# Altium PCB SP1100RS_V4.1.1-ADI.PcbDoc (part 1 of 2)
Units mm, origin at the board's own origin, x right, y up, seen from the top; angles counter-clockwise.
Board outline 126.12 x 87.13 mm, 4 copper layers (TopLayer, GND, PWR, BottomLayer); 154 components, 100 nets, 516 pads, 161 vias.
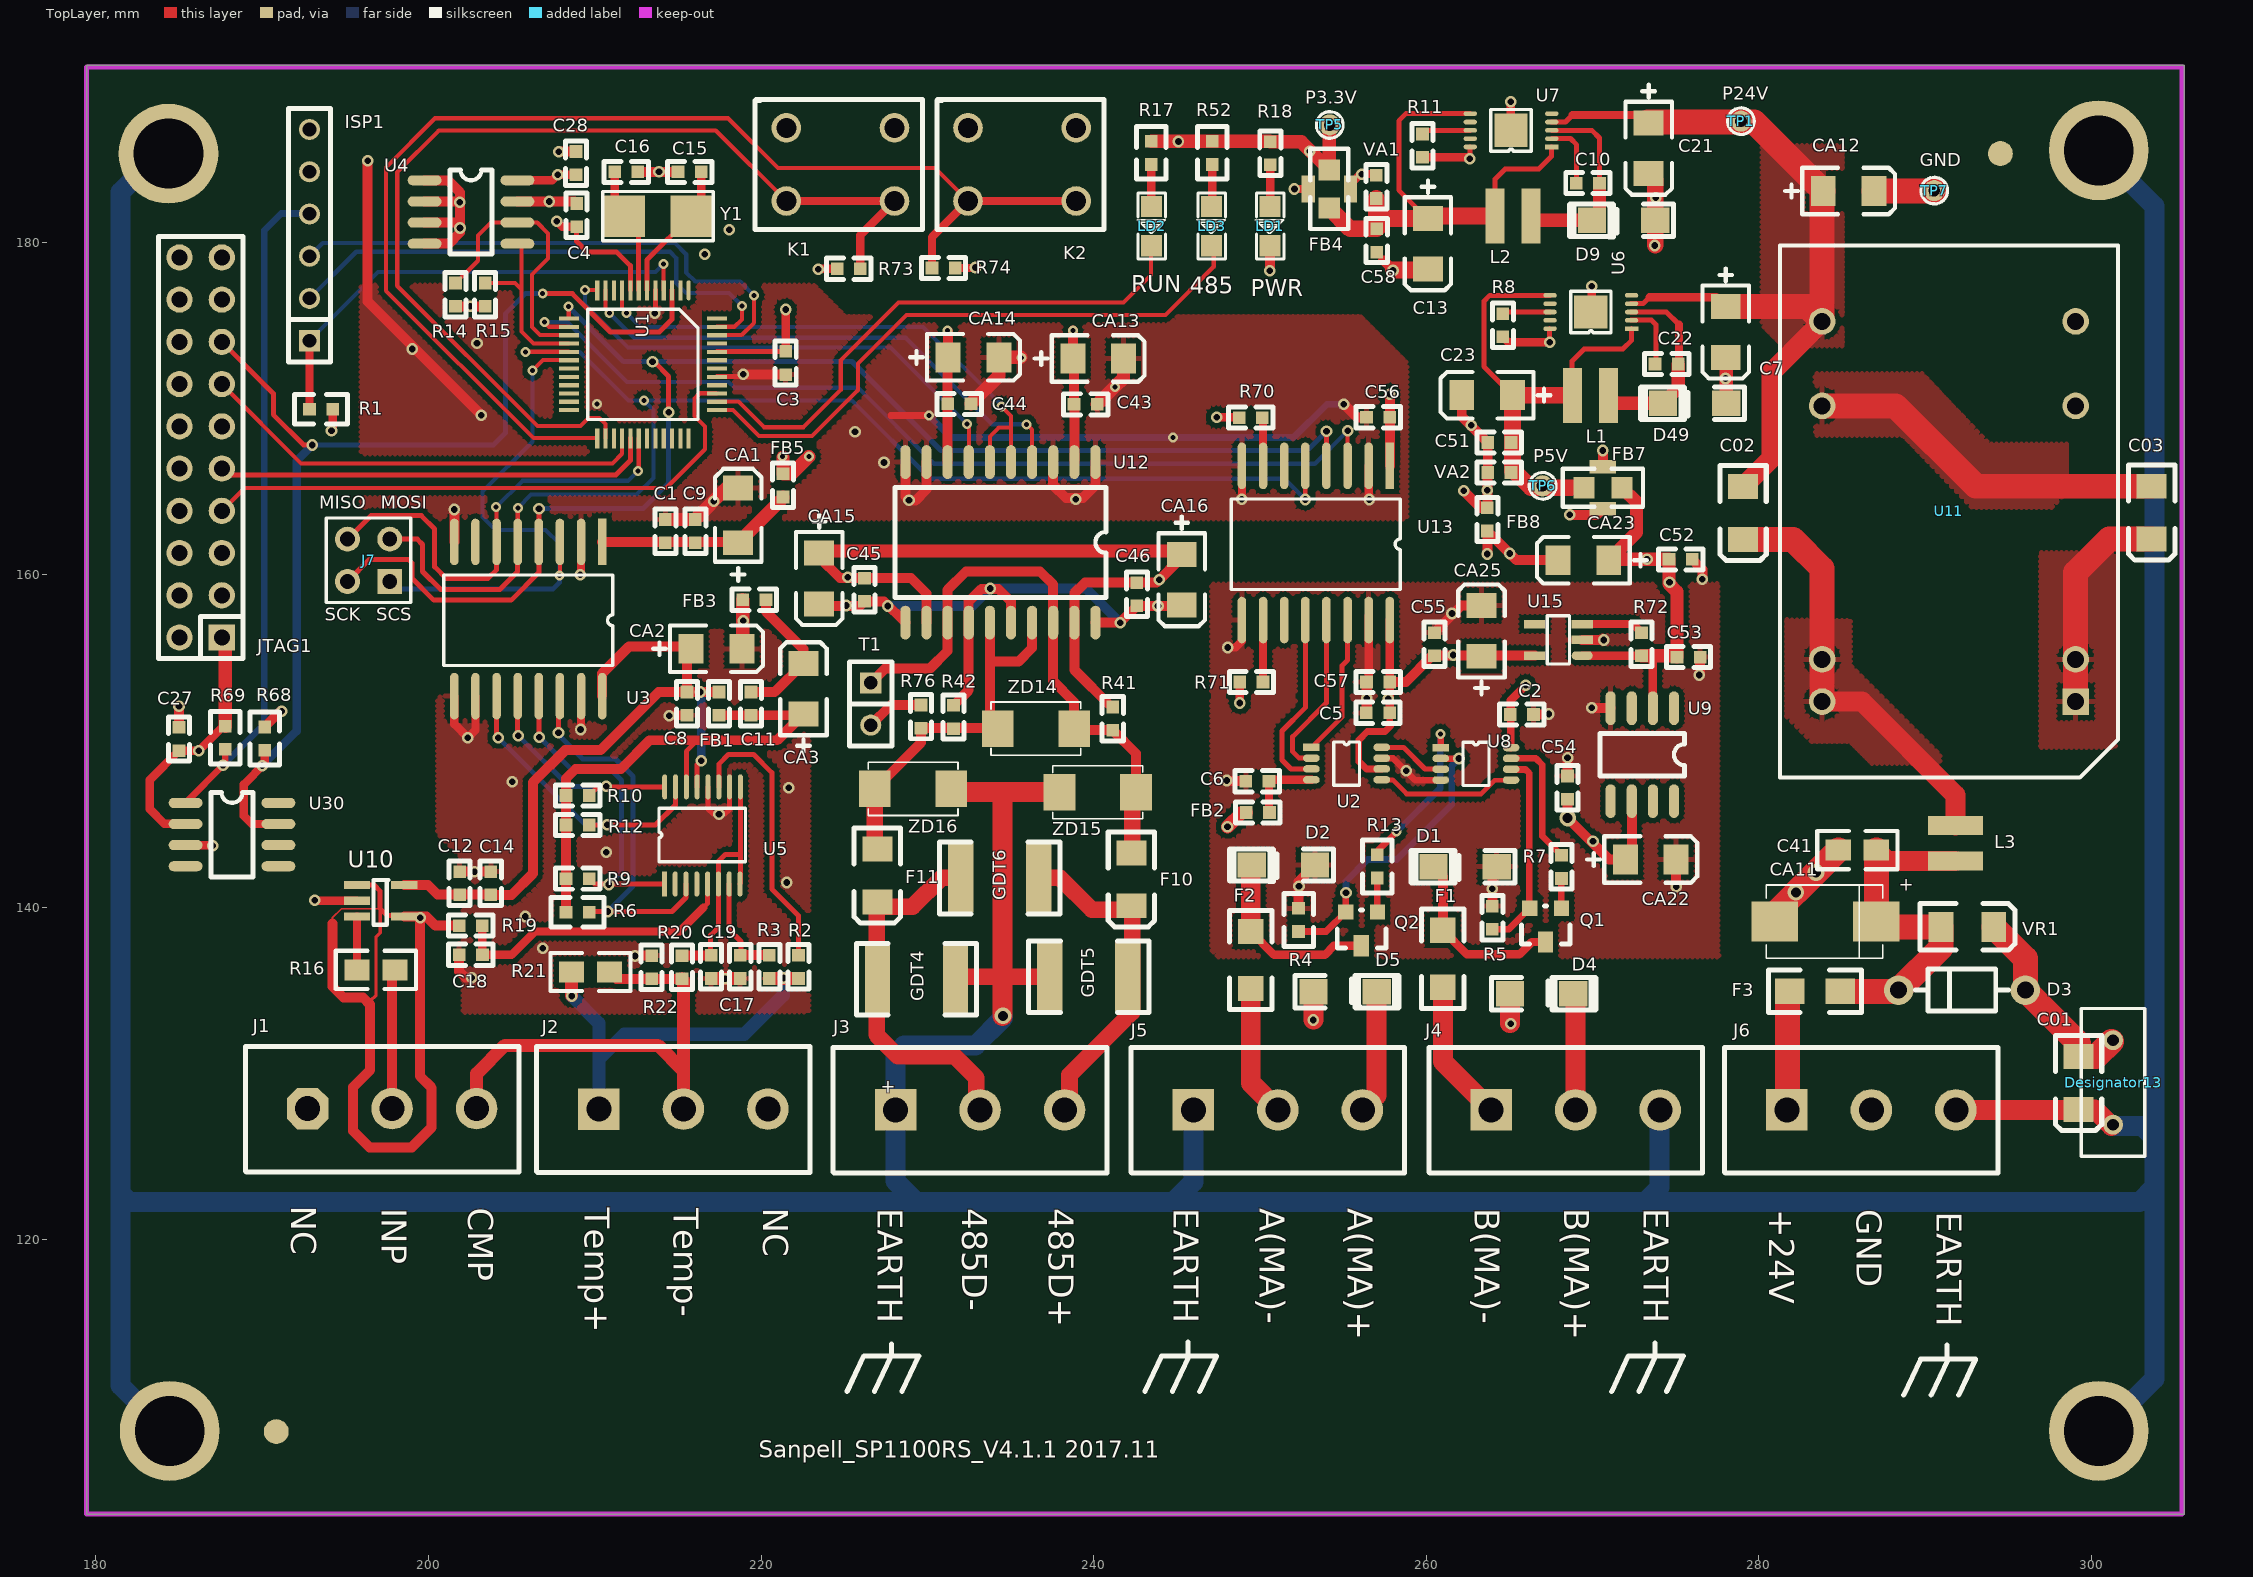
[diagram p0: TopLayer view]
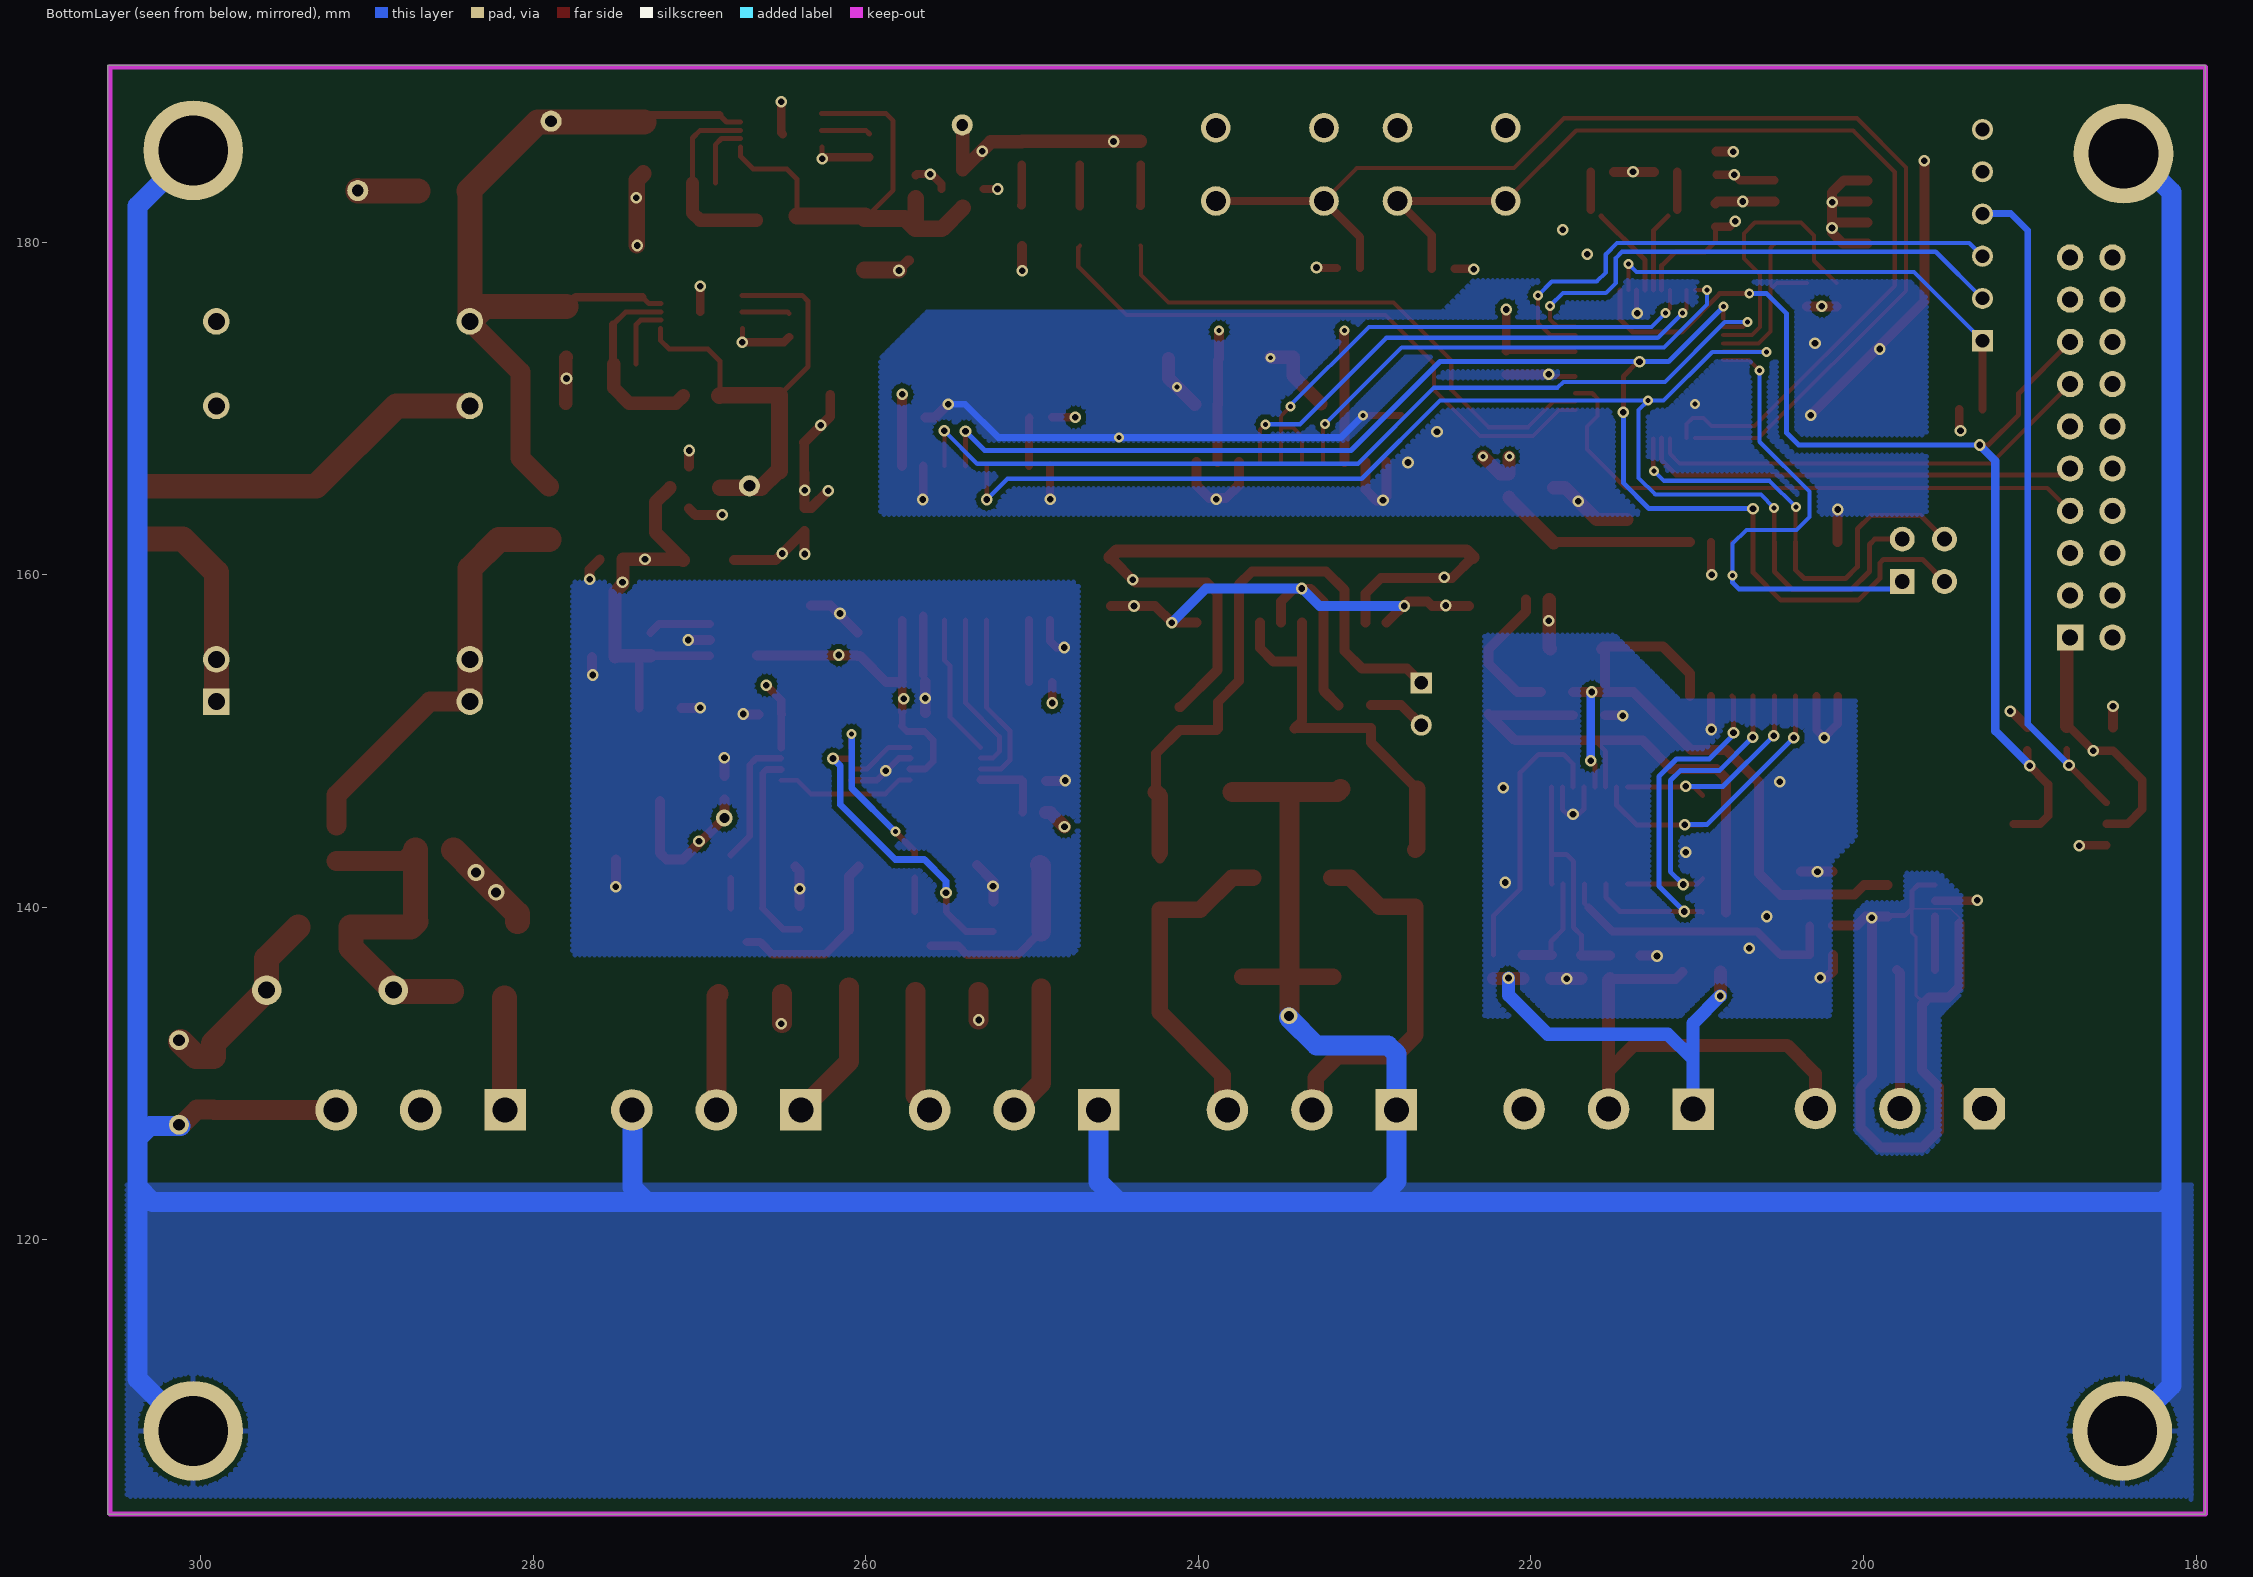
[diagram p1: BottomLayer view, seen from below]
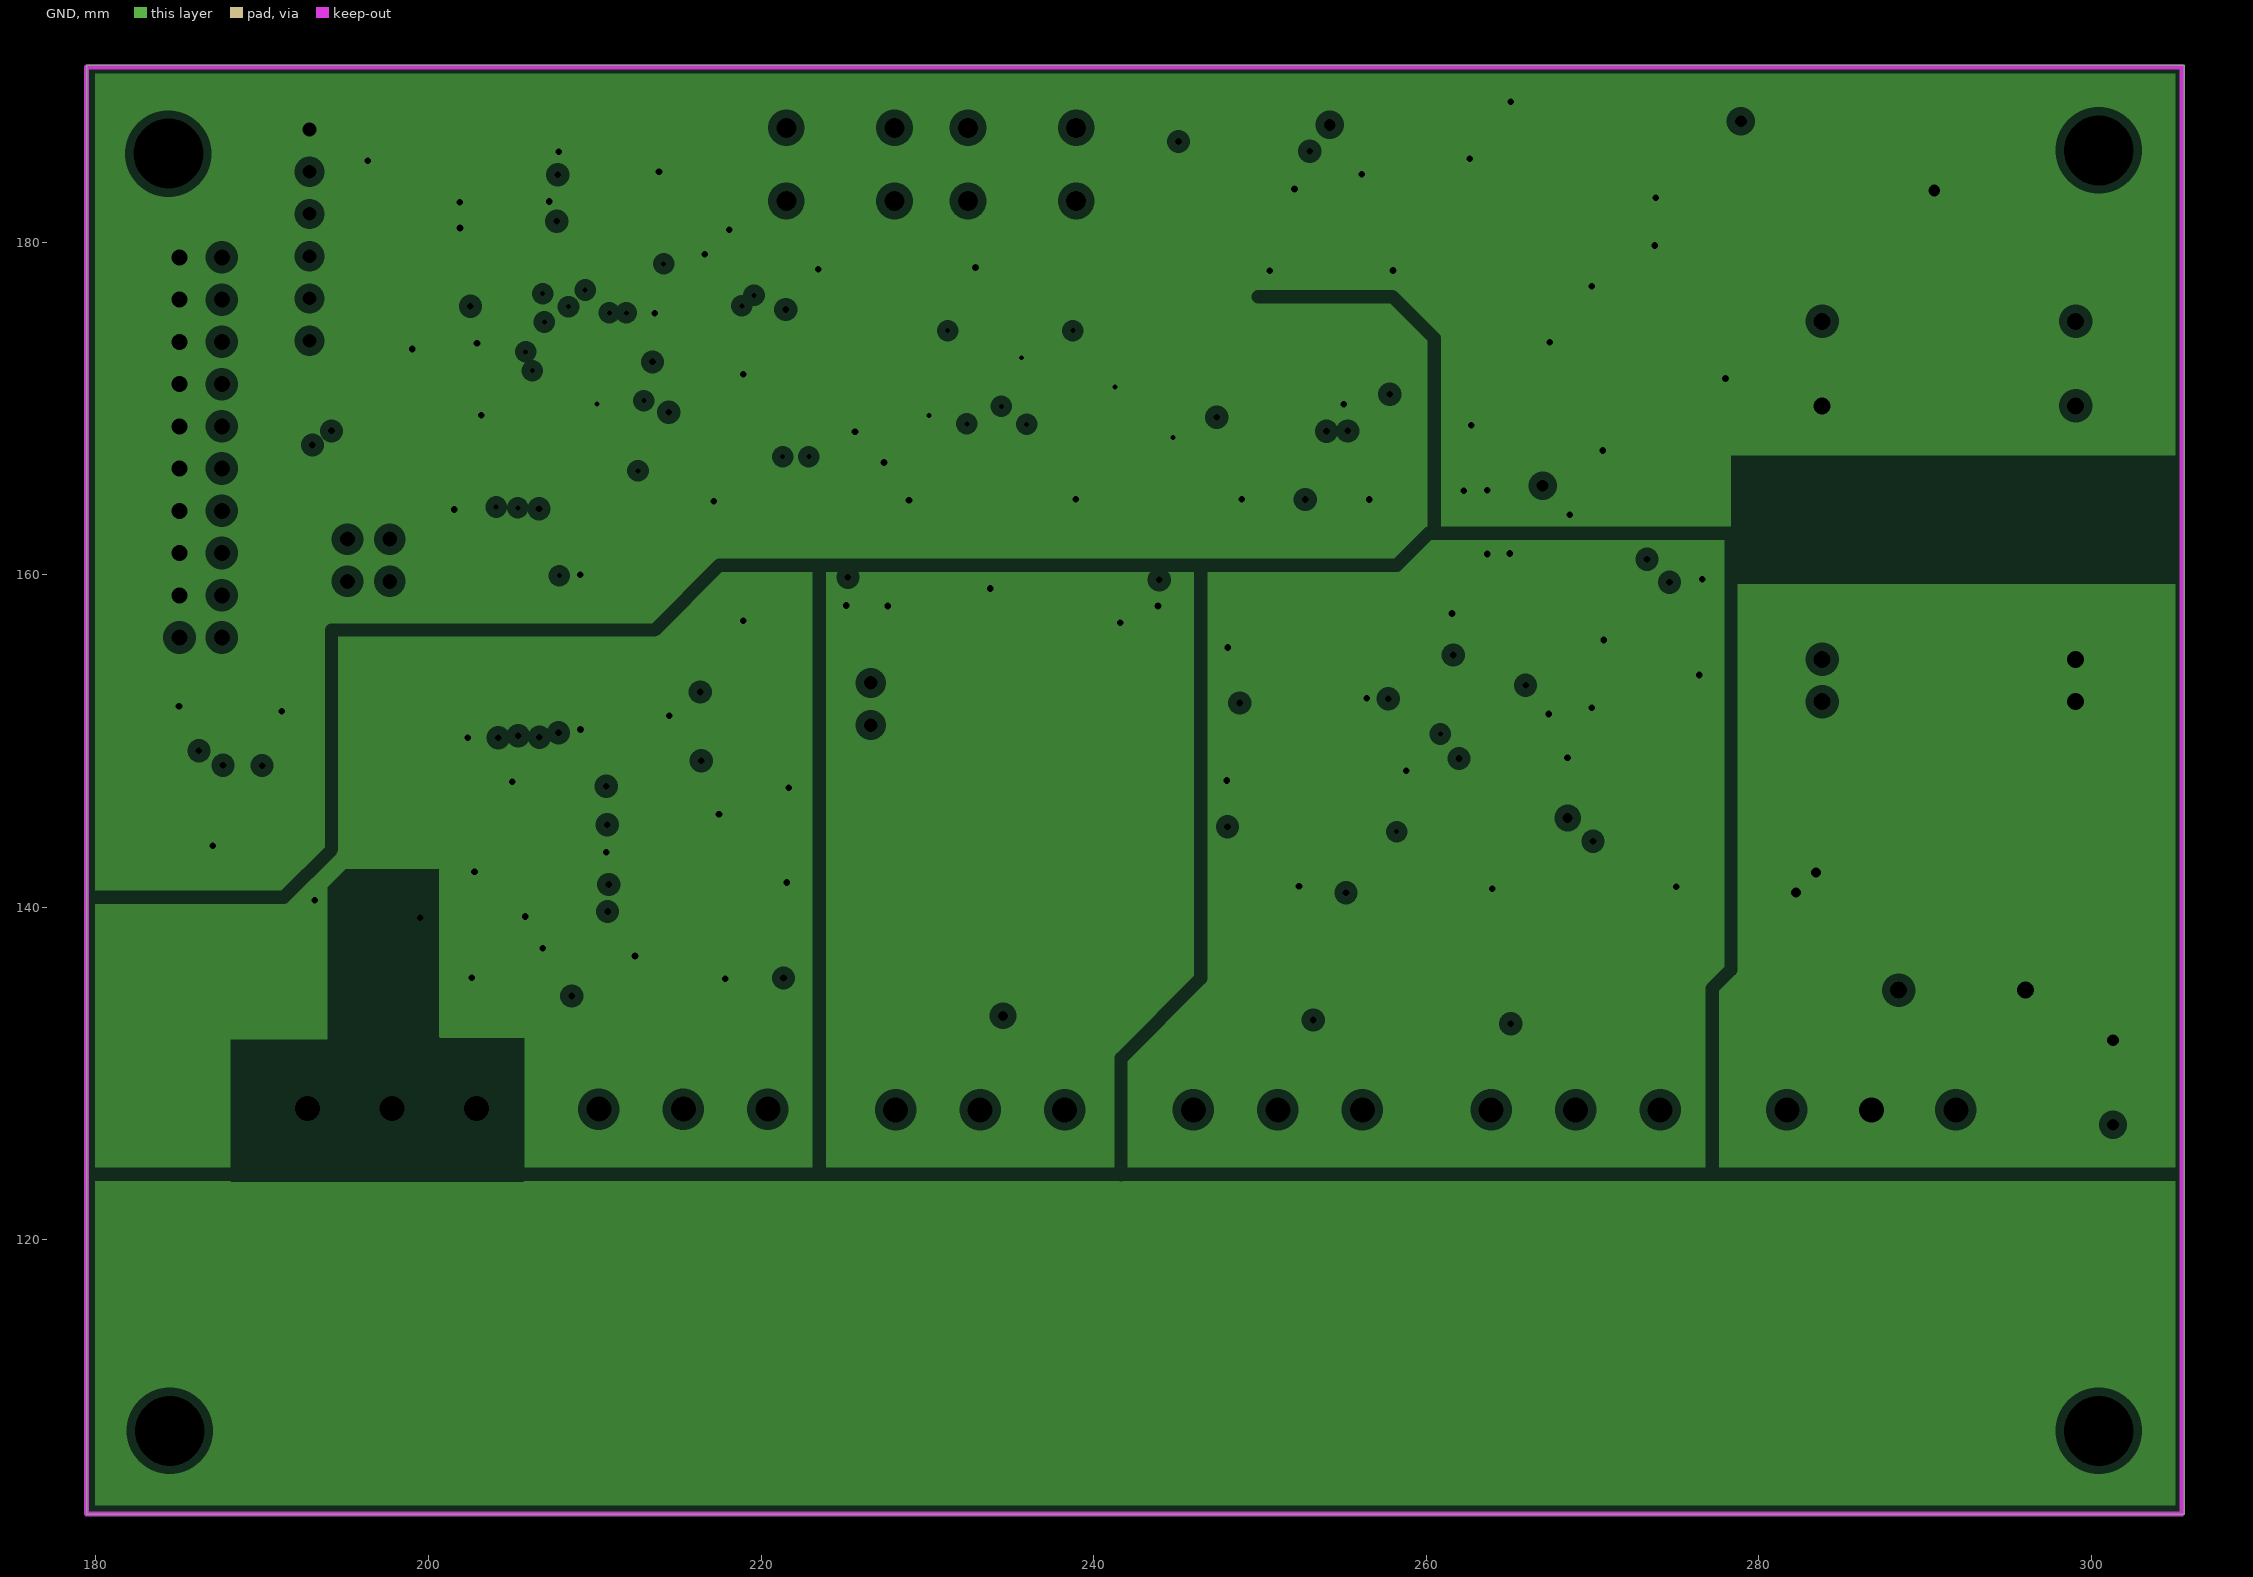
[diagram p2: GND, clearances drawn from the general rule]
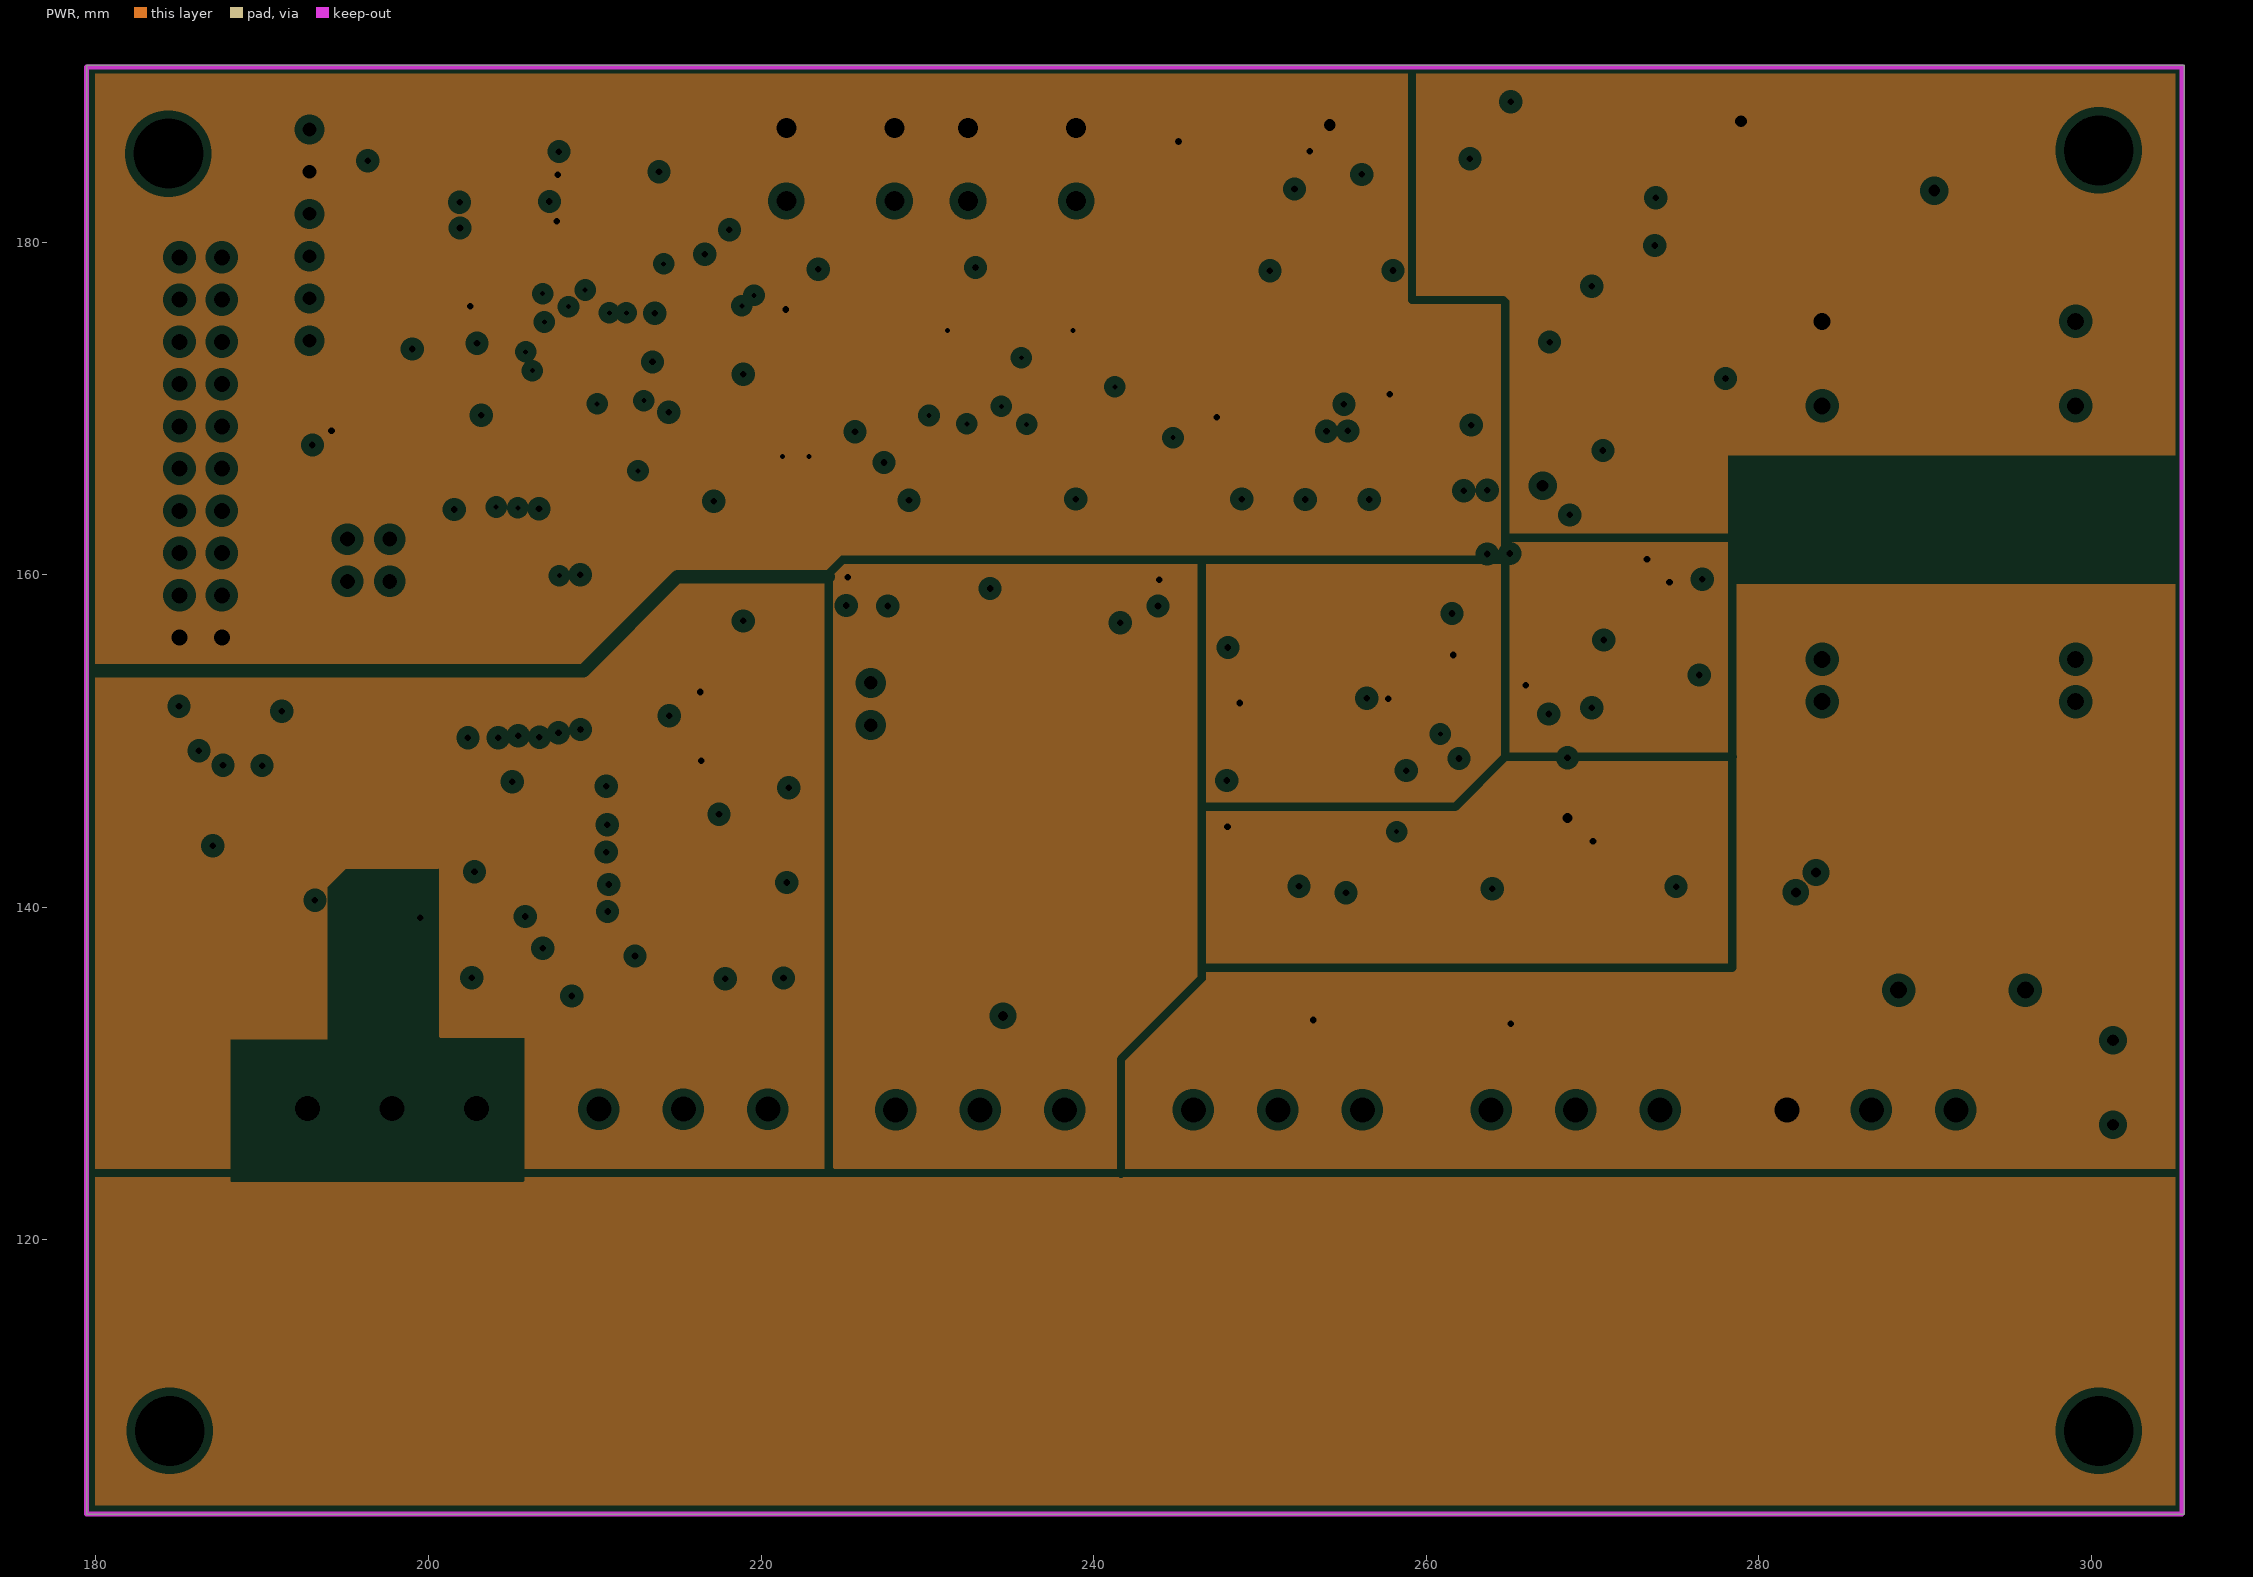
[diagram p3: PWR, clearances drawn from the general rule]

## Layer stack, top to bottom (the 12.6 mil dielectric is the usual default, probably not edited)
TopLayer: signal copper 0.0356
Dielectric: core 0.32, FR-4, Dk 4.8
GND: plane copper 0.0356, net (Multiple Nets)
Dielectric: prepreg 0.32, FR-4, Dk 4.8
PWR: plane copper 0.0356, net (Multiple Nets)
Dielectric: core 0.32, FR-4, Dk 4.8
BottomLayer: signal copper 0.0356

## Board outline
179.45,103.522 305.569,103.522 305.569,190.649 179.45,190.649

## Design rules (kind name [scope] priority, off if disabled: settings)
Clearance Clearance_poly [InPolygon] p1: gap=0.3
Clearance [All] p2: gap=0.15
ComponentClearance [All] p1: gap=0.15 collisioncheckmode=3 verticalgap=0.254 showdistances=FALSE
FabricationTestPointUsage TestPointUsage [All] p1: valid=0 allowmultiple=FALSE
FabricationTestpoint Testpoint [All] p1: side=3 testpointundercomponent=TRUE minsize=1.016 maxsize=2.54 preferedsize=1.524 minholesize=0.508 maxholesize=1.016 preferedholesize=0.813 testpointgrid=0.025 allowsidetop=TRUE allowsidebottom=TRUE usegrid=TRUE gridtolerance=0
HoleSize [All] p1: absolutevalues=TRUE maxlimit=5.08 minlimit=0.025 maxpercent=80.000 minpercent=20.000
MinimumSolderMaskSliver [All] p1: minsoldermaskwidth=0.15
PlaneClearance [All] p1: clearance=0.5
PlaneConnect [All] p1: planeconnectstyle=Relief reliefexpansion=0.5 reliefentries=4 reliefconductorwidth=0.3 reliefairgap=0.3
PolygonConnect PolygonConnect_via [IsVia] p1: connectstyle=Direct reliefconductorwidth=0.254 reliefentries=4 polygonreliefangle="90 Angle"
PolygonConnect [All] p2: connectstyle=Relief reliefconductorwidth=0.3 reliefentries=4 polygonreliefangle="90 Angle"
RoutingVias [All] p1: holewidth=0.305 width=0.61 viastyle="Through Hole" minholewidth=0.254 minwidth=0.508 maxholewidth=2 maxwidth=5
SilkToSilkClearance [All] p1: silktosilkclearance=0
SilkscreenOverComponentPads [All] p1: minsilkscreentomaskgap=0
SolderMaskExpansion [All] p1: expansion=0.102
Width [All] p1: maxlimit=5.08 minlimit=0.1 preferedwidth=0.254
19 further rules are at their usual default settings.

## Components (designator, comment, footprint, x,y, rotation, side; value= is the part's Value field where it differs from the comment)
C1 "10nF" 0603 214.25,161.925 r90 top
C01 "1nF/2kV" 1206#1 299.225,127.975 r270 top
C2 "0.1uF" 0603 265.049,151.593 r0 top
C02 "1nF/2kV" 1206#1 279.05,162.25 r270 top
C3 "0.1uF" 0603 221.484,173.432 r270 top
C03 "1nF/2kV" 1206#1 303.625,162.275 r270 top
C4 "0.1uF" 0603 208.911,180.925 r90 top
C5 "0.1uF" 0603 257.8,151.7 r180 top
C6 "0.1uF" 0603 250.548,147.587 r180 top
C7 "4.7uF/50V" 1206C#1 278.01,176.125 r270 top
C8 "0.1uF" 0603 215.55,152.95 r270 top
C9 "0.1uF" 0603 216.05,163.325 r270 top
C10 "0.47uF" 0603 269.025,183.55 r0 top
C11 "0.1uF" 0603 219.4,151.55 r90 top
C12 "10nF" 0603 201.875,140.75 r90 top
C13 "22uF" 1206C#1 260.1,181.425 r270 top
C14 "0.1uF" 0603 203.75,140.75 r90 top
C15 "22pF" 0603 216.404,184.227 r180 top
C16 "22pF" 0603 211.197,184.227 r0 top
C17 "1uF" 0603 218.75,137.125 r270 top
C18 "1uF" 0603 203.25,137.15 r180 top
C19 "1uF" 0603 217,137.125 r270 top
C21 "4.7uF/50V" 1206C#1 273.375,187.175 r270 top
C22 "0.47uF" 0603 273.76,172.675 r0 top
C23 "22uF" 1206C#1 265.185,170.8 r180 top
C27 "0.1uF" 0603 185,149.425 r90 top
C28 "0.1uF" 0603 208.875,184.05 r90 top
C41 "1uF/50V" 0805#1 287.075,143.45 r180 top
C43 "0.1uF" 0603 238.825,170.25 r0 top
C44 "0.1uF" 0603 231.225,170.275 r0 top
C45 "0.1uF" 0603 226.225,159.797 r270 top
C46 "0.1uF" 0603 242.6,158.128 r90 top
C51 "0.1uF" 0603 265.1,167.95 r180 top
C52 "0.1uF" 0603 274.6,160.925 r0 top
C53 "0.1uF" 0603 275.075,155.05 r0 top
C54 "0.1uF" 0603 268.5,146.5 r90 top
C55 "0.1uF" 0603 260.5,155.125 r90 top
C56 "0.1uF" 0603 257.81,169.471 r180 top
C57 "0.1uF" 0603 257.81,153.556 r180 top
C58 "0.1uF" 0603 257.025,180.8 r270 top
CA1 "10uF" 1206C#2 218.625,161.925 r90 top
CA2 "10uF" 1206C#1 215.8,155.55 r0 top
CA3 "10uF" 1206C#1 222.55,151.625 r90 top
CA11 "100uF/50V" D 287.05,139.15 r180 top
CA12 "10uF/50V" 1206C#1 283.875,183.075 r0 top
CA13 "10uF" 1206C#1 238.75,173 r0 top
CA14 "10uF" 1206C#1 231.25,173.075 r0 top
CA15 "10uF" 1206C#1 223.5,161.3 r270 top
CA16 "10uF" 1206C#1 245.3,161.225 r270 top
CA22 "10uF" 1206C#1 271.975,142.875 r0 top
CA23 "10uF/16V" 1206C#1 270.975,160.875 r180 top
CA25 "10uF" 1206C#1 263.325,155.1 r90 top
D1 "SMF26AG" 1206D 264.05,142.45 r180 top
D2 "SMF26AG" 1206D 253.125,142.55 r180 top
D3 "1N4007" 1N4007 296.025,135.025 r180 top
D4 "CD1607-B140" 1206D 265.233,134.8 r0 top
D5 "CD1607-B140" 1206D 253.408,134.925 r0 top
D9 "CD1607-B140" 1206D 273.575,181.317 r180 top
D49 "CD1607-B140" 1206D 277.846,170.315 r180 top
Designator13 "Comment" RAD-0.2 301.3,129.475 r270 top
F1 "1210L005WR" 1206#2 261,138.625 r270 top
F2 "1210L005WR" 1206#2 249.45,138.554 r270 top
F3 "3A" 1206#3 281.85,134.95 r0 top
F10 "FUSE1" 1206#1 242.275,140.225 r270 top
F11 "FUSE1" 1206#1 227,140.45 r270 top
FB1 "BLM18PG600SN1" 0603 217.475,152.95 r270 top
FB2 "BLM18PG600SN1" 0603 249.178,145.7 r0 top
FB3 "BLM18PG600SN1" 0603 218.9,158.5 r0 top
FB4 "NFM21PC105B1C3" 0805#2 254.175,182.05 r90 top
FB5 "BLM18PG600SN1" 0603 221.325,166.075 r270 top
FB7 "NFM21PC105B1C3" 0805#2 269.475,165.225 r0 top
FB8 "BLM18PG600SN1" 0603 263.675,164.025 r270 top
GDT4 "SMD1812-091" 1812 227,135.675 r0 top
GDT5 "SMD1812-091" 1812 237.363,135.828 r0 top
GDT6 "SMD1812-091" 1812 232.001,141.775 r0 top
ISP1 "" SIP6 192.85,174.075 r90 top
J1 "" PH3-S#1 192.737,127.898 r0 top
J2 "" PH3-S#2 210.255,127.873 r0 top
J3 "" PH3-S#2 228.092,127.823 r0 top
J4 "" PH3-S#2 263.906,127.823 r0 top
J5 "" PH3-S#2 245.999,127.823 r0 top
J6 "" PH3-S#2 281.686,127.823 r0 top
J7 "Header 4" HDR2x2 197.675,159.6 r90 top
JTAG1 "DEBUG" IDC20 187.575,156.225 r90 top
K1 "SW-PB" "SW-PB ANJIAN" 224.776,184.675 r0 top
K2 "SW-PB" "SW-PB ANJIAN" 235.698,184.675 r0 top
L1 "LPS3010-472ML" LPS3010 270.96,170.775 r180 top
L2 "LPS3010-472ML" LPS3010 266.309,181.571 r180 top
L3 "4.7uH" LPS3010 291.825,142.775 r90 top
LD1 "PWR" LED0805 250.61,180.725 r0 top
LD2 "RUN" LED0805 243.5,180.725 r0 top
LD3 "485" LED0805 247.1,180.725 r0 top
Q1 "MMBT3904" SOT-23 268.13,139.952 r180 top
Q2 "MMBT3904" SOT-23 257.063,139.727 r180 top
R1 "10K" 0603 192.85,169.95 r0 top
R2 "0R" 0603 222.25,135.725 r90 top
R3 "10K" 0603 220.5,135.725 r90 top
R4 "100R 1%" 0603 252.325,138.55 r90 top
R5 "100R 1%" 0603 263.975,138.675 r90 top
R6 "100K" 0603 208.275,139.7 r0 top
R7 "10K" 0603 268.13,141.738 r90 top
R8 "49.9K" 0603 264.61,174.303 r90 top
R9 "100K" 0603 208.275,141.725 r0 top
R10 "100K" 0603 208.275,146.725 r0 top
R11 "49.9K" 0603 259.775,185.103 r90 top
R12 "100K" 0603 208.275,144.95 r0 top
R13 "10K" 0603 257.063,141.765 r90 top
R14 "10K" 0603 201.631,177.541 r270 top
R15 "10K" 0603 203.409,177.541 r270 top
R16 "1M" 0805#1 198,136.25 r180 top
R17 "1K" 0603 243.475,184.675 r90 top
R18 "1K" 0603 250.625,184.65 r90 top
R19 "10K" 0603 201.85,138.9 r0 top
R20 "10K" 0603 215.25,135.7 r90 top
R21 "5K 0.1%" 0805#1 210.9,136.125 r180 top
R22 "5K 0.1%" 0603 213.425,135.7 r90 top
R41 "47K" 0603 241.15,152.05 r270 top
R42 "47K" 0603 231.575,150.75 r90 top
R52 "1K" 0603 247.125,184.675 r90 top
R68 "10K" 0603 190.15,150.85 r270 top
R69 "10K" 0603 187.775,149.5 r90 top
R70 "4.7K" 0603 250.15,169.45 r180 top
R71 "4.7K" 0603 248.793,153.556 r0 top
R72 "4.7k" 0603 272.95,156.522 r270 top
R73 "10K" 0603 224.578,178.4 r0 top
R74 "10K" 0603 231.675,178.45 r180 top
R76 "120R" 0603 229.625,150.775 r90 top
T1 "" SIP2 226.6,153.5 r270 top
TP1 "P24V" "TEST POINT" 278.925,187.275 r0 top
TP5 "P3.3V" "TEST POINT" 254.2,187.05 r0 top
TP6 "P5V" "TEST POINT" 267,165.35 r0 top
TP7 "GND" "TEST POINT" 290.55,183.1 r0 top
U1 "LPC1316FBD48" LPC1316 212.9,172.65 r0 top
U2 "LT2602IMS8" LT2602 255.225,148.6 r0 top
U3 "ADuM5401ARWZ" ADUM1401 210.45,161.975 r270 top
U4 "AT24C64D" SO-8 199.767,183.719 r0 top
U5 "AD7793BRU" AD7793 216.475,144.325 r90 top
U6 "LT3971IMSE-5" LT3971 269.9,175.8 r90 top
U7 "LT3971IMSE-3.3" LT3971 265.1,186.725 r90 top
U8 "AD8646ARMZ" AD8646 262.95,148.775 r0 top
U9 "ADR03ARZ" SO-8 274.9,151.975 r270 top
U10 "AD8603AUJ" AD8603 197.125,140.4 r90 top
U11 "URB2424ZP-6WR3" URB2424ZP-6WR3 299.05,152.375 r90 top
U12 "ADM2587E" SOL-20 240.11,166.775 r270 top
U13 "ADuM1401ARW" ADUM1401 257.81,166.55 r270 top
U15 "TPS76033DBVR" SOT23-5A 269.375,155.15 r90 top
U30 "MAX708S" SO-8 185.396,146.285 r0 top
VA1 "V3.5MLA0603N" 0603 257,184.025 r270 top
VA2 "V5.5MLA0603N" 0603 263.7,166.15 r0 top
VR1 "14D560" 1206#1 294,138.825 r0 top
Y1 "12MHz" CY5.4X4.6 215.769,181.56 r180 top
ZD14 "SMBJ12" ZD 238.825,150.75 r180 top
ZD15 "SMBJ12" ZD 242.55,146.925 r180 top
ZD16 "SMBJ12" ZD 231.45,147.125 r180 top

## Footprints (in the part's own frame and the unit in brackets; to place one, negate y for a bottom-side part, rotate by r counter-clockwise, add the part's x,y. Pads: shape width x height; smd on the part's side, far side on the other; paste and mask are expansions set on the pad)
1N4007 [mil]
  round 70 hole 40: 1(0,0) 2(300,0)
  silkscreen extent 40,-50 260,50
0603 [mil]
  rect 30x30 smd: 1(0,0) 2(55,0)
  silkscreen extent -25,-25 80,25
0805#1 [mil]
  rect 60x50 smd: 1(0.39,0.31) 2(90.39,0.31)
  silkscreen extent -50,-45 140,45
0805#2 [mil]
  rect 50x50 smd: 1(0.39,0.31) 2(90.39,0.31)
  silkscreen extent -50,-45 140,45
1206#1 [mm]
  rect 1.5x1.8 smd: 1(-3.048,0) 2(0.127,0)
  silkscreen extent -4.32,-1.4 1.4,1.4
1206#2 [mm]
  rect 1.524x1.524 smd: 1(0,0) 2(3.429,0)
  silkscreen extent -1.27,-1.27 4.7,1.27
1206#3 [mm]
  rect 1.778x1.524 smd: 1(0,0) 2(3.048,0)
  silkscreen extent -1.27,-1.27 4.32,1.27
1206C#1 [mm]
  rect 1.5x1.8 smd: 1(0,0) 2(3.048,0)
  silkscreen extent -2.29,-1.4 4.32,1.4
1206C#2 [mm]
  rect 1.5x1.8 smd: 1(0,0) 2(3.302,0)
  silkscreen extent -2.29,-1.4 4.44,1.4
1206D [mm]
  rect 1.7x1.524 smd: 1(-0.19,0.003) 2(3.61,0.003)
  silkscreen extent -1.3,-0.97 4.96,0.99
1812 [mil]
  rect 60x164.37 smd: 1(0,0) 2(185,0)
  silkscreen extent -50,-85 235,85
AD7793 [mm]
  rect 1.5x0.3 smd: 1(-2.921,2.286)
  oval 1.5x0.3 smd: 2(-2.921,1.636) 3(-2.921,0.986) 4(-2.921,0.336) 5(-2.921,-0.314) 6(-2.921,-0.964) 7(-2.921,-1.614) 8(-2.921,-2.264) 9(2.921,-2.286) 10(2.921,-1.636) 11(2.921,-0.986) 12(2.921,-0.336) 13(2.921,0.314) 14(2.921,0.964) 15(2.921,1.614) 16(2.921,2.264)
  silkscreen extent -1.59,-2.59 1.64,2.61
AD8603 [mm]
  rect 0.5x1.575 smd: 1(0.95,1.425) 2(0,1.425) 3(-0.95,1.425) 4(-0.95,-1.425) 5(0.95,-1.425)
  silkscreen extent -1.45,-0.48 1.25,0.42
AD8646 [mm]
  rect 1x0.45 smd: 1(-2.074,0.833)
  oval 1x0.45 smd: 2(-2.074,0.183) 3(-2.074,-0.467) 4(-2.074,-1.117) 5(2.156,-1.117) 6(2.156,-0.467) 7(2.156,0.183) 8(2.156,0.833)
  silkscreen extent -0.74,-1.44 0.82,1.16
ADUM1401 [mm]
  rect 2.8x0.51 smd: 1(0,0)
  oval 2.8x0.51 smd: 2(0,-1.27) 3(0,-2.54) 4(0,-3.81) 5(0,-5.08) 6(0,-6.35) 7(0,-7.62) 8(0,-8.89) 9(9.271,-8.89) 10(9.271,-7.62) 11(9.271,-6.35) 12(9.271,-5.08) 13(9.271,-3.81) 14(9.271,-2.54) 15(9.271,-1.27) 16(9.271,0)
  silkscreen extent 1.99,-9.53 7.43,0.64
CY5.4X4.6 [mm]
  rect 2.5x2.5 smd: 1(-0.025,0) 2(4,0)
  silkscreen extent -1.35,-1.49 5.28,1.49
D [mil]
  rect 110x94.49 smd: 1(0,0) 2(240,0)
  silkscreen extent -16,-87 260,87
HDR2x2 [mm] "Connector; Header; 2x2 Position"
  rect 1.5x1.5 hole 0.9: 1(0,0)
  round 1.5 hole 0.9: 2(0,2.54) 3(2.54,0) 4(2.54,2.54)
  silkscreen extent -1.27,-1.27 3.81,3.81
IDC20 [mil]
  rect 62x62 hole 38: 1(0,0)
  round 62 hole 38: 2(0,100) 3(100,0) 4(100,100) 5(200,0) 6(200,100) 7(300,0) 8(300,100) 9(400,0) 10(400,100) 11(500,0) 12(500,100) 13(600,0) 14(600,100) 15(700,0) 16(700,100) 17(800,0) 18(800,100) 19(900,0) 20(900,100)
  silkscreen extent -50,-50 950,150
LED0805 [mm]
  rect 1.27x1.27 smd: A(-0.01,1.426) K(-0.01,-0.944)
  silkscreen extent -0.88,-1.75 0.83,2.24
LPC1316 [mm]
  oval 0.25x1.2 smd: 1(2.75,4.45)
  rect 0.25x1.2 smd: 2(2.25,4.45) 3(1.75,4.45) 4(1.25,4.45) 5(0.75,4.45) 6(0.25,4.45) 7(-0.25,4.45) 8(-0.75,4.45) 9(-1.25,4.45) 10(-1.75,4.45) 11(-2.25,4.45) 12(-2.75,4.45) 25(-2.75,-4.45) 26(-2.25,-4.45) 27(-1.75,-4.45) 28(-1.25,-4.45) 29(-0.75,-4.45) 30(-0.25,-4.45) 31(0.25,-4.45) 32(0.75,-4.45) 33(1.25,-4.45) 34(1.75,-4.45) 35(2.25,-4.45) 36(2.75,-4.45)
  rect 1.2x0.25 smd: 13(-4.45,2.75) 14(-4.45,2.25) 15(-4.45,1.75) 16(-4.45,1.25) 17(-4.45,0.75) 18(-4.45,0.25) 19(-4.45,-0.25) 20(-4.45,-0.75) 21(-4.45,-1.25) 22(-4.45,-1.75) 23(-4.45,-2.25) 24(-4.45,-2.75) 37(4.45,-2.75) 38(4.45,-2.25) 39(4.45,-1.75) 40(4.45,-1.25) 41(4.45,-0.75) 42(4.45,-0.25) 43(4.45,0.25) 44(4.45,0.75) 45(4.45,1.25) 46(4.45,1.75) 47(4.45,2.25) 48(4.45,2.75)
  silkscreen extent -3.31,-3.31 3.31,3.31
LPS3010 [mm]
  rect 1.14x3.3 smd: 1(0,0) 2(2.16,0)
LT2602 [mm]
  rect 1x0.45 smd: 1(-2.127,1.023)
  oval 1x0.45 smd: 2(-2.127,0.373) 3(-2.127,-0.277) 4(-2.127,-0.927) 5(2.103,-0.927) 6(2.103,-0.277) 7(2.103,0.373) 8(2.103,1.023)
  silkscreen extent -0.79,-1.25 0.77,1.35
LT3971 [mm]
  rect 0.28x0.8 smd: 1(-1,-2.45)
  oval 0.28x0.8 smd: 2(-0.5,-2.45) 3(0,-2.45) 4(0.5,-2.45) 5(1,-2.45) 6(1,2.45) 7(0.5,2.45) 8(0,2.45) 9(-0.5,2.45) 10(-1,2.45)
  rect 2x2 smd: 11(0,0)
  silkscreen extent -1.25,-1.21 1.25,1.22
PH3-S#1 [mm]
  oct 2.5x2.5 hole 1.5: 1(0,0)
  round 2.5 hole 1.5: 2(5.08,0) 3(10.16,0)
  silkscreen extent -3.75,-3.81 12.7,3.75
PH3-S#2 [mm]
  rect 2.5x2.5 hole 1.5: 1(0,0)
  round 2.5 hole 1.5: 2(5.08,0) 3(10.16,0)
  silkscreen extent -3.75,-3.81 12.7,3.75
RAD-0.2 [mm] "Radial Cap, Thru-Hole; 2 Leads; 0.2 in Pin Spacing"
  round 1.2 hole 0.7: 1(-2.54,0) 2(2.54,0)
  silkscreen extent -4.44,-1.91 4.44,1.91
SIP2 [mil]
  rect 50x50 hole 32: 1(0,0)
  round 50 hole 32: 2(100,0)
  silkscreen extent -50,-50 150,50
SIP6 [mil]
  rect 50x50 hole 32: 1(0,0)
  round 50 hole 32: 2(100,0) 3(200,0) 4(300,0) 5(400,0) 6(500,0)
  silkscreen extent -50,-50 550,50
SO-8 [mil]
  oval 80x24 smd: 1(0,0) 2(0,-50) 3(0,-100) 4(0,-150) 5(220,-150) 6(220,-100) 7(220,-50) 8(220,0)
  silkscreen extent 60,-175 160,25
SOL-20 [mil]
  oval 80x24 smd: 1(0,0) 2(0,-50) 3(0,-100) 4(0,-150) 5(0,-200) 6(0,-250) 7(0,-300) 8(0,-350) 9(0,-400) 10(0,-450) 11(380,-450) 12(380,-400) 13(380,-350) 14(380,-300) 15(380,-250) 16(380,-200) 17(380,-150) 18(380,-100) 19(380,-50) 20(380,0)
  silkscreen extent 60,-475 320,25
SOT23-5A [mil]
  oval 20x50 smd: 1(-0.49,-0.18)
  rect 20x50 smd: 2(36.91,-0.18) 3(74.32,-0.18) 4(74.32,112.02) 5(-0.49,112.02)
  silkscreen extent -20,30 94,82
SOT-23 [mil]
  rect 36x36 smd: 1(0,0) 2(75,0)
  rect 36x50 smd: 3(38,80)
  silkscreen extent -20,-5 95,85
"SW-PB ANJIAN" [mm]
  round 1.778 hole 1.2: 1(-3.25,2.2) 1(3.25,2.2) 2(-3.25,-2.2) 2(3.25,-2.2)
  silkscreen extent -5.13,-3.93 4.93,3.9
"TEST POINT" [mil]
  round 50 hole 28: 1(0,0)
  silkscreen extent -31,-31 31,31
URB2424ZP-6WR3 [mm] "isolated DC-DC converter, 6W"
  rect 1.6x1.6 hole 1.016: 2(0,0)
  round 1.6 hole 1.016: 3(2.54,0) 9(17.78,0) 11(22.86,0) 14(22.86,15.24) 16(17.78,15.24) 22(2.54,15.24) 23(0,15.24)
  silkscreen extent -4.57,-2.54 27.43,17.78
ZD [mm]
  rect 1.9x2.2 smd: 1(0,0) 2(4.6,0)
  silkscreen extent -0.4,-1.6 5,1.6

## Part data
C1 C8 C9 C11 C12 C14 C17 C18 C19: library part C, "电?"
C01 C2 C02 C3 C03 C4 C5 C6 C10 C15 C16 C22 C27 C28 C41 C51 C52 C53 C54 C55 C56 C57 C58 CA23: library part CAP, "Capacitor"
C7 C13 C21 C23 CA13 CA14 CA15 CA16 CA22 CA25: library part CAPE, "¼«Ð"
C43 C44 C45 C46: library part CA, "电?"
CA1 CA2 CA3 CA11 CA12: library part C, "¼«Ð"
D1 D2: library part ZENER3, "Zener Diode"
D3: library part "Diode 1N4007", "1 Amp General Purpose Rectifier"
D4 D5 D9 D49: library part DIODE, "Diode"
F1 F2: library part FUSE2, "Fuse"
F3: library part FUSE1, "Fuse"
F10 F11: "Fuse"
FB1: library part Inductor
FB2 FB4 FB5 FB7 FB8: library part Inductor, "Inductor"
FB3 L1 L2 L3: library part INDUCTOR
GDT4 GDT5 GDT6: library part BT90
ISP1: library part CON6, "Connector"
J1 J2 J3 J4 J5 J6: library part CON3, "Connector"
J7: "Header, 4-Pin"
JTAG1: library part "HEADER 10X2"
K1 K2: "Switch"
LD1 LD2 LD3: library part LED
R1 R4 R5 R7 R8 R11 R13 R14 R15 R17 R18 R52 R68 R69 R70 R71 R72 R73 R74: library part RES, "电?"
R2 R3 R6 R9 R10 R12 R16 R19 R20 R21 R22: library part R, "电?"
R41 R42 R76: library part RE, "电?"
T1: library part CON2, "Connector"
TP1 TP5 TP6 TP7: library part PAD
U2: library part LT2602
U3 U13: library part ADUM1401, "1Mbps Data Rate, 100ns Propagation delay"
U4: library part 24C01/02/04/08/16
U5: library part AD7793
U6 U7: library part LT3971
U8: library part AD8646
U9: library part ADR02
U10: library part AD8603
U15: library part TPS76033
U30: library part SP708
VA1 VA2: library part "D Zener", "Zener Diode"
VR1: library part "Res Varistor", "Varistor (Voltage-Sensitive Resistor)"
Y1: library part CRYSTAL, "Crystal"
ZD14 ZD15 ZD16: library part SMBJ, "瞬变"

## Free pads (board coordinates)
  round 6 hole 4.2: 0(184.37,185.323) 4(300.442,185.522) 6(184.442,108.522) 7(300.442,108.522)
  rect 0.8x1.6 smd: 0(252.9,183.2) 0(255.45,183.2)
  rect 1.6x0.8 smd: 0(270.625,163.975) 0(270.625,166.5)
  round 1.5 smd: ""(190.85,108.475) ""(294.525,185.325)

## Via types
v1: diameter 0.7, hole 0.4, TopLayer to BottomLayer, 127 vias
v2: diameter 0.6, hole 0.3, TopLayer to BottomLayer, 30 vias
v3: diameter 1, hole 0.6, TopLayer to BottomLayer, 4 vias

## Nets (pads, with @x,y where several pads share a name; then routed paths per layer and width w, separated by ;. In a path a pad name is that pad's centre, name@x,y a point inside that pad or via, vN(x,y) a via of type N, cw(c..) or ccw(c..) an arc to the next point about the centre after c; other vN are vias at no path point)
24VGND_IN: C01.1 C03.2 C41.2 CA11.2 D3.1 Designator13.1 J6.2 U11.2 U11.3 VR1.2 | length 31.2
  TopLayer w1.5: CA11.2@280.954,139.15 280.954,139.617 v3(283.437,142.1) C41.2@284.779,143.442 ; VR1.2@294.127,138.825 296.025,136.927 D3.1@296.025,135.025 299.225,131.825 C01.1@299.225,131.148 ; U11.2@299.05,152.375 U11.3@299.05,154.915 299.05,160.125 301.073,162.148 C03.2@303.625,162.148 ; C01.1@299.225,131.023 300.283,131.023 Designator13.1@301.2,131.94
  other v3: 282.225,140.9
+24V: C02.1 C7.1 C21.1 CA12.1 TP1.1 U6.4 U7.4 U11.14 | length 50.6
  TopLayer w0.3: U7.4@267.527,187.229 268.379,187.229 268.8,187.65 ; U6.4@272.318,176.306 273.035,176.306 273.424,176.695
  TopLayer w0.5: 268.8,187.65 272.9,187.65 C21.1@273.325,187.225 ; 273.424,176.695 277.44,176.695 C7.1@278.01,176.125
  TopLayer w0.8: C21.1@273.325,187.225 C21.1@273.375,187.175 ; C7.1@278.01,176.05 C7.1@278.01,176.125
  TopLayer w1.2: C02.1@279.05,165.298 280.775,167.023 280.775,172.2 U11.14@283.81,175.235
  TopLayer w1.5: C21.1@273.325,187.225 279.725,187.225 CA12.1@283.875,183.075 283.81,183.01 U11.14@283.81,175.235 282.92,176.125 C7.1@278.01,176.125
+24V_IN: D4.1 D5.1 F3.1 J6.1 | length 10.2
  TopLayer w1.2: v1@253.217,133.242 D5.1@253.217,134.928 ; v1@265.042,133.033 D4.1@265.042,134.803
  TopLayer w1.5: J6.1@281.686,127.823 281.725,127.862 F3.1@281.725,134.55
  other v1: 265.075,133 253.2,133.225
A_UART5: F10.2 GDT5.2 GDT6.2 J3.3 | length 20.1
  TopLayer w0.8: J3.3@238.252,127.823 J3.3@238.552,128.123
  TopLayer w1: GDT6.2@236.7,141.775 237.975,141.775 239.889,139.861 242.316,139.861 242.316,133.691 238.552,129.927 J3.3@238.552,128.123
B_UART5: F11.2 GDT4.1 GDT6.1 J3.2 | length 22.6
  TopLayer w1: GDT6.1@232.001,141.775 230.85,141.775 229.121,140.046 226.949,140.046 226.949,132.334 228.219,131.064 231.636,131.064 232.95,129.75 232.95,128.045 J3.2@233.172,127.823
CURA: F1.2 J4.1 | length 8.6
  TopLayer w1.2: F1.2@261,135.196 261,130.729 J4.1@263.906,127.823
CURB: F2.2 J5.2 | length 8
  TopLayer w1.2: F2.2@249.45,135.125 249.45,129.452 J5.2@251.079,127.823
DA_CS#: U2.1 U13.14 | length 8.6
  TopLayer w0.3: U2.1@253.111,149.619 254.95,151.458 254.95,154.546 255.27,154.866 U13.14@255.27,157.279
DA_DIN: U2.3 U13.12 | length 11
  TopLayer w0.3: U13.12@252.73,157.279 252.73,152.005 251.333,150.608 251.333,148.857 251.871,148.319 U2.3@253.111,148.319
DA_SCLK: U2.2 U13.13 | length 10.1
  TopLayer w0.3: U2.2@253.111,148.969 252.364,148.969 251.968,149.365 251.968,150.268 254,152.3 U13.13@254,157.279
DE485: U1.9 U12.5 U12.6 | length 33
  TopLayer w0.25: U1.9@211.642,177.115 211.642,176.008 v2(211.9,175.75) ; U12.6@233.76,166.775 233.76,168.31 234.3,168.85 235.03,168.85 ; v2(234.45,170.125) 235.03,169.545 235.03,168.85 ; U12.5@235.03,166.775 235.03,168.85
  BottomLayer w0.25: v2(211.9,175.75) 212.75,174.9 229.75,174.9 234.45,170.2 v2(234.45,170.125)
DVDD: C11.1 CA3.1 FB1.2 R6.1 R9.1 R10.1 R12.1 U5.14 | length 32
  TopLayer w0.3: U5.14@215.511,147.246 215.511,149.386 216.175,150.05
  TopLayer w0.6: R6.1@208.275,139.7 R12.1@208.275,144.95 R10.1@208.275,146.725 208.275,147.75 208.85,148.325 211.575,148.325 213.3,150.05 216.175,150.05 220.975,150.05 CA3.1@222.478,151.553 ; FB1.2@217.475,151.553 CA3.1@222.478,151.553 ; CA3.1@222.55,151.625 CA3.1@222.478,151.553
E\X\R\S\T\: ISP1.4 R69.1 U30.1 | length 40.5
  TopLayer w0.4: U30.1@185.394,146.287 U30.1@185.396,146.285 187.775,148.663 R69.1@187.775,149.5
  BottomLayer w0.4: v1(187.65,148.55) 190.125,151.025 190.125,180.7 191.15,181.725 192.82,181.725 ISP1.4@192.85,181.695
EARTH: C01.2 Designator13.2 GDT4.2 GDT5.1 J3.1 J4.3 J5.1 J6.3 pad.0@184.37,185.323 pad.4 pad.6 pad.7 ZD15.2 ZD16.1 | length 349.2
  TopLayer w0.8: J3.1@227.584,127.315 J3.1@228.092,127.823
  TopLayer w1: GDT4.2@231.902,135.828 234.525,135.828 GDT5.1@237.363,135.828
  TopLayer w1.2: ZD16.1@231.45,147.125 231.65,146.925 ZD15.2@237.95,146.925 ; v3@234.525,133.475 234.525,135.828 234.525,146.825 ; J6.3@291.846,127.823 299.2,127.823 C01.2@299.225,127.848 300.212,127.848 Designator13.2@301.2,126.86
  BottomLayer w1.2: pad.6@184.15,108.585 181.483,111.252 181.483,122.825 ; pad.0@184.15,185.674 181.483,183.007 181.483,122.825 ; v3@234.567,133.367 232.899,131.699 228.6,131.699 228.092,131.191 J3.1@228.092,127.823 228.092,123.533 229.35,122.275 ; J5.1@245.999,127.823 245.999,123.499 244.775,122.275 ; J4.3@274.066,127.823 274.025,127.782 274.025,123.15 273.15,122.275 ; pad.4@300.442,185.522 303.784,182.18 303.784,126.125 ; pad.7@300.875,108.725 303.784,111.634 303.784,123.175 ; Designator13.2@301.2,126.86 303.049,126.86 303.784,126.125 ; 181.483,122.825 182.033,122.275 229.35,122.275 ; 229.35,122.275 244.775,122.275 ; 244.775,122.275 273.15,122.275 ; 273.15,122.275 302.884,122.275 303.784,123.175 ; 303.784,123.175 303.784,126.125
  other v3: 234.55,133.475
GND: C1.2 C03.1 C3.2 C4.2 C7.2 C9.1 C13.2 C15.2 C16.2 C21.2 C23.2 C27.2 C28.2 C43.2 C44.2 C51.2 C56.2 C58.2 CA1.2 CA12.2 CA13.2 CA14.2 D9.1 D49.1 FB8.1 ISP1.6 JTAG1.4 JTAG1.6 JTAG1.8 JTAG1.10 JTAG1.12 JTAG1.14 JTAG1.16 JTAG1.18 JTAG1.20 LD1.K pad.0@252.9,183.2 pad.0@255.45,183.2 pad.0@270.625,163.975 pad.0@270.625,166.5 R8.1 R11.1 R68.1 R73.1 R74.1 TP7.1 U1.5 U1.41 U3.2 U3.8 U4.1 U4.2 U4.3 U4.4 U4.7 U6.10 U6.11 U7.10 U7.11 U11.16 U12.1 U12.3 U12.9 U12.10 U13.2 U13.8 U30.3 VA1.1 VA2.1 | length 175.6
  TopLayer w0.3: v1(213.61,175.718) 213.642,175.75 U1.5@213.642,177.115 ; U1.41@217.342,171.915 218.79,171.915 v1(218.925,172.05) ; v1(262.627,185.02) U7.10@262.627,185.729 ; v1(267.418,173.991) U6.10@267.418,174.806
  TopLayer w0.4: 227.8,169.575 v2(230.1,169.575)
  TopLayer w0.5: U30.3@185.396,143.745 186.98,143.745 v1(187.025,143.7) ; v1(209.125,160) 209.18,160.055 U3.2@209.18,161.975 ; v1@223.475,178.4 R73.1@224.578,178.4 ; R74.1@231.675,178.45 v1@232.875,178.45 ; v1(248.9,164.55) 248.92,164.57 U13.8@248.92,166.55 ; v1(252.075,183.2) pad.0@252.9,183.2 ; pad.0@255.45,183.2 255.45,183.5 256.05,184.1 256.925,184.1 VA1.1@257,184.025 ; U13.2@256.54,166.55 256.54,164.56 v1(256.575,164.525) ; R11.1@259.775,185.103 262.544,185.103 v1(262.627,185.02) ; R8.1@264.61,174.303 264.922,173.991 v1(267.418,173.991) ; U7.11@264.987,186.491 265.075,186.579 v1(265.075,188.45) ; U6.11@269.96,175.806 v1(269.96,177.35) v1@269.96,177.387
  TopLayer w0.6: C27.2@185,150.822 v1(185,152.1) ; R68.1@190.15,150.85 191.1,151.8 v1(191.175,151.8) ; v1(196.35,184.9) 196.35,176.425 v1(203.175,169.6) ; U4.4@199.767,179.909 201.234,179.909 201.9,180.575 v1(201.9,180.85) 201.9,181.35 ; U4.3@199.767,181.179 201.729,181.179 201.9,181.35 ; U4.2@199.767,182.449 201.751,182.449 v1@201.9,182.3 ; U4.1@199.767,183.719 201.181,183.719 201.9,183 v1@201.9,182.3 ; v1(201.55,163.925) 201.56,163.915 U3.8@201.56,161.975 ; U4.7@205.355,182.449 v1(207.275,182.449) 208.784,182.449 C4.2@208.911,182.322 ; v1(207.847,185.447) C28.2@208.85,185.447 ; C16.2@212.594,184.227 v1(213.864,184.227) C15.2@215.007,184.227 ; v1@218.94,172.035 C3.2@221.484,172.035 ; U12.10@228.68,166.775 228.68,164.695 v1(228.9,164.475) 229.3,164.475 229.95,165.125 U12.9@229.95,166.775 ; U12.3@237.57,166.775 237.57,165.378 238.332,164.616 239.348,164.616 240.11,165.378 U12.1@240.11,166.775 ; v1(250.6,178.275) LD1.K@250.6,179.781 ; v1(255.05,170.25) 255.829,169.471 C56.2@256.413,169.471 ; 257.4,178.903 257.451,178.903 v1@258.027,178.327 ; C23.2@262.137,170.8 262.137,169.516 C51.2@263.703,167.95 263.7,167.947 VA2.1@263.7,166.15 263.675,166.125 v1(263.675,165.075) FB8.1@263.675,164.025 263.275,164.025 v1(262.25,165.05) ; v1(268.625,163.6) 270.25,163.6 pad.0@270.625,163.975 ; pad.0@270.625,166.5 v1(270.625,167.475) ; 201.9,181.35 v1@201.9,182.3
  TopLayer w0.8: C1.2@214.25,163.322 216.047,163.322 C9.1@216.05,163.325 217.952,165.227 CA1.2@218.625,165.227 ; C44.2@232.622,170.275 234.298,171.951 CA14.2@234.298,173.075 v2@235.625,173.075 ; C43.2@240.222,170.25 v2(241.275,171.303) 241.798,171.826 CA13.2@241.798,173 ; C7.2@278.01,173.077 278.036,173.051 D49.1@278.036,170.312
  TopLayer w1: v1@258.027,178.327 C13.2@260.1,178.327 ; C21.2@273.375,184.127 273.765,183.737 D9.1@273.765,181.314 v1@273.765,179.815
  TopLayer w1.5: U11.16@283.81,170.155 288.22,170.155 293.052,165.323 C03.1@303.625,165.323 ; CA12.2@286.923,183.075 290.525,183.075 TP7.1@290.55,183.1
  BottomLayer w0.4: v2@230.075,169.6 231.425,168.25 v2(244.775,168.25) 252.025,168.25 254.025,170.25 v1(255.05,170.25)
  other v1: 217.15,164.425 238.925,164.55 227.4,166.75 225.65,168.6 262.7,169 278,171.8 199.025,173.575 202.925,173.925 258,178.3 223.45,178.375 232.9,178.475 216.625,179.275 273.75,179.8 218.1,180.75 201.875,182.4 273.8,182.675 256.125,184.075
  other v2: 210.15,170.275 235.65,173.05
GND_COM: C45.2 C46.1 CA15.2 CA16.2 R42.2 U12.11 U12.14 U12.16 U12.20 | length 37.5
  TopLayer w0.6: CA15.2@223.725,158.125 225.95,158.125 C45.2@226.225,158.4 227.403,158.4 U12.11@228.68,157.123 ; R42.2@231.575,152.147 232.49,153.062 U12.14@232.49,157.123 232.49,158.393 233.247,159.15 234.273,159.15 235.03,158.393 U12.16@235.03,157.123 ; U12.20@240.11,157.123 v1(241.595,157.123) C46.1@242.6,158.128 CA16.2@245.25,158.128
  BottomLayer w0.6: v1(227.625,158.125) 232.725,158.125 v1(233.775,159.175) 239.543,159.175 v1(241.595,157.123)
  other v1: 243.875,158.125 225.125,158.15
GND_ISO: C8.2 C12.2 C14.2 C17.2 C18.2 C19.2 CA2.2 FB3.1 R22.2 U3.9 U3.10 U3.15 U5.10 U5.12 U10.2 | length 24.9
  TopLayer w0.3: v1(209.15,150.7) v1@209.18,150.73 ; U5.12@216.811,147.246 216.811,145.914 217.125,145.6 v1(217.475,145.6) 217.825,145.6 218.111,145.886 U5.10@218.111,147.246
  TopLayer w0.5: v1@193.175,140.4 U10.2@195.7,140.4 ; U3.9@201.56,152.704 201.56,151.015 v1(202.375,150.2) 202.83,150.655 U3.10@202.83,152.704 ; v1@209.18,150.73 U3.15@209.18,152.704
  TopLayer w0.6: C18.2@201.853,137.15 201.853,136.153 201.85,136.15 202.225,135.775 v1(202.6,135.775) ; C12.2@201.875,142.147 C14.2@203.75,142.147 ; v1(212.425,137.075) 212.447,137.097 R22.2@213.425,137.097 ; v1@214.503,151.553 C8.2@215.55,151.553
  TopLayer w0.8: C19.2@217,135.728 C17.2@218.75,135.728 ; CA2.2@218.848,155.55 218.9,155.602 FB3.1@218.9,158.5
  other v1: 217.85,135.7 206.875,137.55 205.825,139.45 193.175,140.425 221.55,141.5 202.775,142.15 210.7,143.325 221.675,147.2 205.05,147.55 214.475,151.525 218.925,157.225
IAGND: C2.2 C5.2 C6.2 C52.2 C53.2 C54.2 C55.2 C57.2 CA22.2 CA23.2 CA25.2 D1.1 D2.1 FB8.2 R4.2 R5.2 U2.7 U8.4 U9.4 U13.9 U13.15 U15.2 | length 36.5
  TopLayer w0.4: U2.7@257.341,148.969 258.006,148.969 259.331,147.644 U8.4@260.858,147.644
  TopLayer w0.5: v1(248.075,155.628) 248.539,155.628 248.92,156.009 U13.9@248.92,157.279 ; 256.54,153.977 U13.15@256.54,157.279 U13.15@256.54,157.533
  TopLayer w0.6: v1(248,147.625) 248.038,147.587 C6.2@249.151,147.587 ; 252.331,140.361 252.331,141.563 D2.1@253.315,142.547 ; C55.2@260.5,156.522 262.126,158.148 CA25.2@263.3,158.148 ; v1(263.675,161.25) FB8.2@263.675,162.628 265.428,160.875 CA23.2@267.927,160.875 ; R5.2@263.975,140.072 263.975,142.182 D1.1@264.24,142.447 ; C2.2@266.446,151.593 267.343,151.593 v1(267.375,151.625) ; C54.2@268.5,147.897 v1(268.5,149) ; U15.2@269.38,156.088 270.662,156.088 v1(270.675,156.075) ; v1@269.975,151.975 U9.4@271.09,151.975 ; CA22.2@275.023,142.875 275.023,141.252 v1(275.025,141.25) ; C52.2@275.997,160.925 276.6,160.322 v1(276.6,159.725) ; v1(276.425,153.975) 276.472,154.022 C53.2@276.472,155.05
  TopLayer w0.635: C5.2@256.403,151.7 256.413,151.71 C57.2@256.413,153.556
  other v1: 263.975,141.125 252.35,141.275 258.8,148.225 269.95,152 256.425,152.575 261.55,157.675 265.025,161.275
IREF2.5V: C6.1 FB2.2 U2.4 | length 4.5
  TopLayer w0.5: FB2.2@250.575,145.7 250.548,145.727 C6.1@250.548,147.587 250.634,147.673 U2.4@253.098,147.673
ISP_RXD: ISP1.3 U1.46 | length 33.2
  TopLayer w0.25: U1.46@217.342,174.415 218.84,174.415 219.575,175.15 v2(219.575,176.8)
  BottomLayer w0.25: ISP1.3@192.85,179.155 193.645,179.95 214.825,179.95 215.5,179.275 215.5,178.175 216.05,177.625 218.75,177.625 v2(219.575,176.8)
ISP_TXD: ISP1.2 U1.47 | length 31.9
  TopLayer w0.25: U1.47@217.342,174.915 218.415,174.915 218.85,175.35 v2(218.85,176.175)
  BottomLayer w0.25: ISP1.2@192.85,176.615 195.66,179.425 214.525,179.425 214.9,179.05 214.9,177.55 215.5,176.95 218.075,176.95 v2(218.85,176.175)
ISPEN: ISP1.1 R1.1 U1.4 | length 28.9
  TopLayer w0.25: U1.4@214.142,177.115 214.142,178.692 v2(214.15,178.7)
  TopLayer w0.5: R1.1@192.85,169.95 ISP1.1@192.85,174.075
  BottomLayer w0.25: ISP1.1@192.85,174.075 196.975,178.2 213.65,178.2 v2(214.15,178.7)
JTAG_RST: U1.35
JTAG_TCK: JTAG1.9 U1.29 | length 26.4
  TopLayer w0.3: JTAG1.9@187.575,166.385 187.96,166 211.275,166 212.142,166.867 U1.29@212.142,168.215
JTAG_TDI: U1.32
JTAG_TDO: U1.34
JTAG_TMS: U1.33
LED_S1: LD3.K U1.37 | length 37
  TopLayer w0.25: U1.37@217.342,169.915 218.31,169.915 219.875,168.35 223.075,168.35 225.825,171.1 225.825,172.7 228.75,175.625 244.325,175.625 247.225,178.525 247.225,179.671 LD3.K@247.115,179.781
LED_S2: LD2.K U1.38 | length 33.4
  TopLayer w0.25: U1.38@217.342,170.415 218.635,170.415 220.175,168.875 222.55,168.875 224.791,171.116 224.791,172.891 228.275,176.375 241.8,176.375 243.45,178.025 243.45,179.766 LD2.K@243.49,179.806
MISO1: J7.4 U1.30 U3.6 | length 27.8
  TopLayer w0.25: v2(204.075,164.075) 204.1,164.05 U3.6@204.1,161.975 ; v2(212.6,166.25) 212.65,166.3 U1.30@212.65,168.2
  TopLayer w0.3: J7.4@195.135,162.14 196.545,163.55 199.575,163.55 200.375,162.75 200.375,160.475 201.075,159.775 203.575,159.775 204.1,160.3 U3.6@204.1,161.975
  BottomLayer w0.25: v2(204.075,164.075) 205.65,165.65 212,165.65 v2(212.6,166.25)
MOSI1: J7.3 U1.17 U3.5 U13.5 | length 83.1
  TopLayer w0.25: U3.5@205.37,161.975 205.37,164.02 v2(205.375,164.025) ; v2(205.85,173.4) 205.865,173.415 U1.17@208.442,173.415 ; v1(252.725,164.525) 252.725,166.545 U13.5@252.73,166.55
  TopLayer w0.3: J7.3@197.675,162.14 199.335,162.14 199.65,161.825 199.65,160.2 200.725,159.125 204.3,159.125 205.37,160.195 U3.5@205.37,161.975
  BottomLayer w0.25: v2(205.375,164.025) 206.175,164.825 212.525,164.825 213.525,165.825 213.525,169.9 v2(212.95,170.475) ; v2(205.85,173.4) 209.1,173.4 212.025,170.475 v2(212.95,170.475) ; v1(252.725,164.525) 251.475,165.775 230.175,165.775 225.475,170.475 v2(212.95,170.475)
NetC02_2: C02.2 L3.2 U11.22 U11.23 | length 25.6
  TopLayer w1.2: U11.23@283.81,152.375 286.2,152.375 291.825,146.75 L3.2@291.825,144.935
  TopLayer w1.5: C02.2@279.05,162.123 282.052,162.123 283.81,160.365 U11.22@283.81,154.915 U11.23@283.81,152.375
NetC10_1: C10.1 U7.2 | length 4
  TopLayer w0.3: U7.2@267.527,186.229 268.678,186.229 269.051,185.856 C10.1@269.051,183.55
NetC10_2: C10.2 D9.2 L2.1 U7.3 | length 11.6
  TopLayer w0.3: U7.3@267.527,186.729 269.956,186.729 270.422,186.263 C10.2@270.422,183.55
  TopLayer w0.8: L2.1@266.566,181.314 D9.2@269.965,181.314 270.422,181.771 C10.2@270.422,183.55
NetC11_2: C11.2 CA3.2 FB3.2 | length 8.6
  TopLayer w0.6: C11.2@219.4,152.947 220.824,152.947 CA3.2@222.55,154.673 222.55,155.525 220.297,157.778 FB3.2@220.297,158.5
NetC13_1: C13.1 C58.1 FB4.1 L2.2 U7.1 U7.6 VA1.2 | length 30.6
  TopLayer w0.3: C13.1@260.05,181.425 259.975,181.5 258.35,183.125 258.35,187.3 258.775,187.725 U7.6@262.65,187.725 ; L2.2@264.149,181.571 264.149,183.799 264.75,184.4 266.775,184.4 267.527,185.152 U7.1@267.527,185.729
  TopLayer w1: FB4.1@254.167,182.06 255.427,180.8 C58.1@257.025,180.8 ; VA1.2@257,182.628 257,180.825 C58.1@257.025,180.8 ; C13.1@259.975,181.5 260.046,181.571 L2.2@264.149,181.571 ; C13.1@260.1,181.425 260.05,181.425 257.65,181.425 C58.1@257.025,180.8
NetC15_1: C15.1 U1.6 Y1.1 | length 9.3
  TopLayer w0.3: U1.6@213.142,177.115 213.142,178.933 215.769,181.56 Y1.1@215.794,181.56 Y1.1@214.753,180.519
  TopLayer w0.5: Y1.1@216.404,181.941 C15.1@216.404,184.227
NetC16_1: C16.1 U1.7 Y1.2 | length 7.1
  TopLayer w0.3: Y1.2@211.769,181.56 212.642,180.687 U1.7@212.642,177.115
  TopLayer w0.5: Y1.2@211.197,181.941 C16.1@211.197,184.227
